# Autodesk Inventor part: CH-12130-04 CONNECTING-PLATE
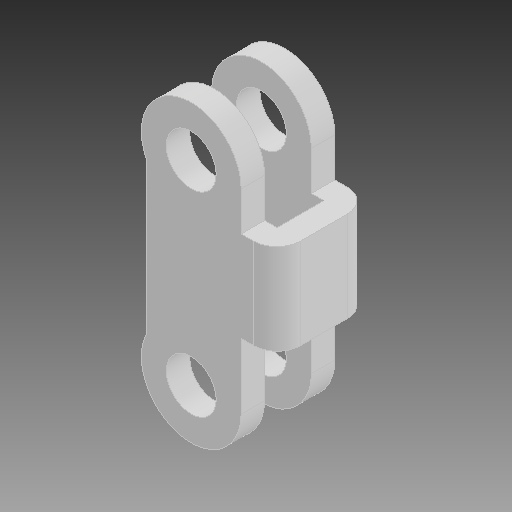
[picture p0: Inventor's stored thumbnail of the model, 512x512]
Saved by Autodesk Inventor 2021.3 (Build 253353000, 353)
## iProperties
Created: 2020-03
Part Number: CH-12130-04 CONNECTING-PLATE
Material: Ogólny
Document SubType Name: Modeling
Designer: Przemyslaw Krecisz
Density: 1 g/cm^3
Appearance: Domyślna
Author: Przemyslaw Krecisz
Revision Number: ÈÎºÎ
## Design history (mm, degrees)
feature "Ô²½Ç1"
node "Bryła1"
